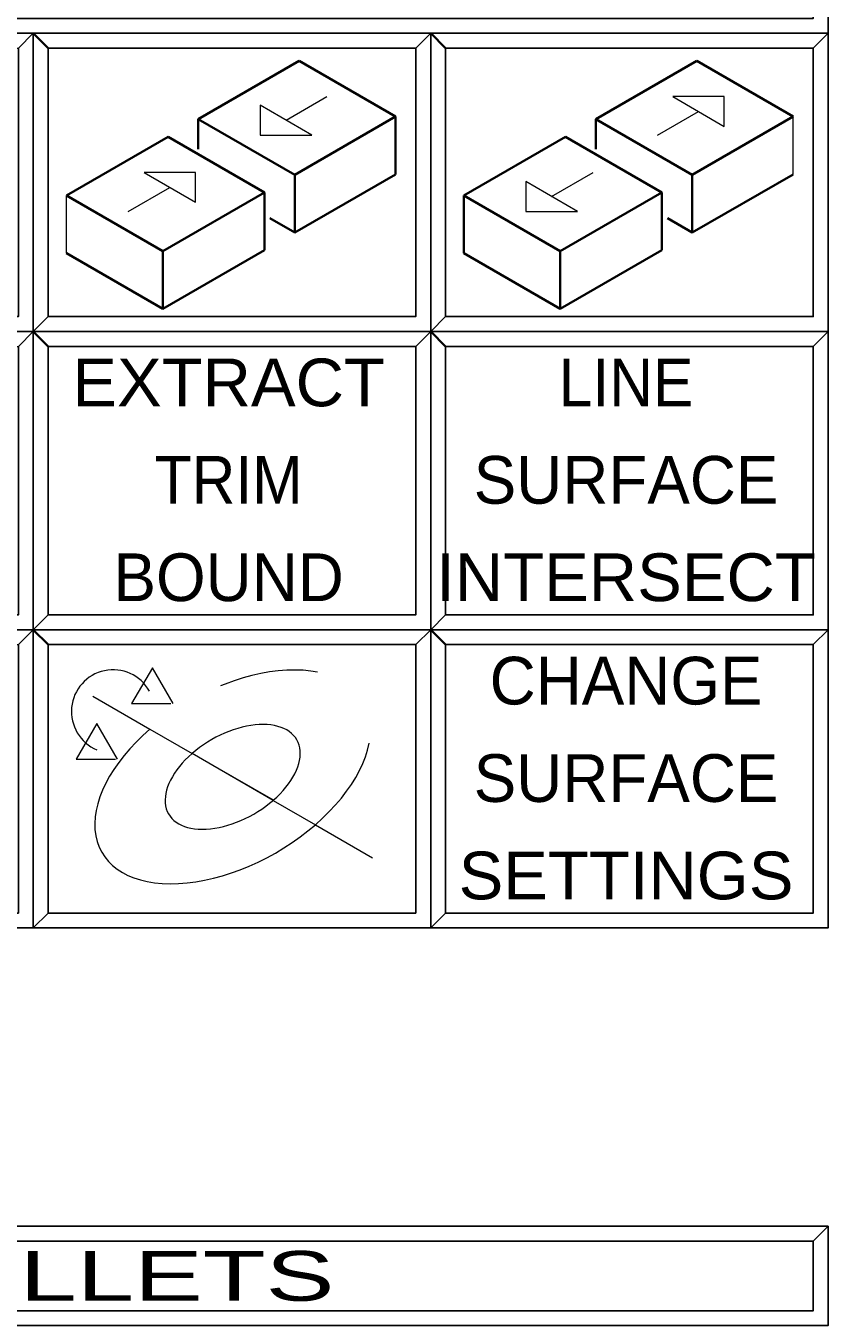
# Model space of a CAD drawing. Extents: x 95906.9 to 95918.9, y 90964.8 to 90972.9.
# Drawn here: x 95915.322 to 95916.13, y 90966.869 to 90968.169 of the extents above; entities that cross this region are included whole.
import ezdxf
from ezdxf.enums import TextEntityAlignment as Align

# ---------------------------------------------------------------- set-up
doc = ezdxf.new("R2010")
doc.units = 0
doc.header["$LTSCALE"] = 0.019
doc.linetypes.add('MEDIUM_DASHED', pattern=[4.5, 3, -1.5])
for name, color, linetype, lineweight in [('1', 7, 'Continuous', 25), ('11', 7, 'Continuous', 25), ('18', 7, 'Continuous', 25), ('2', 7, 'Continuous', 13), ('3', 7, 'Continuous', 25), ('4', 7, 'Continuous', 35), ('6', 7, 'Continuous', 35), ('7', 7, 'Continuous', 35)]:
    doc.layers.add(name, color=color, linetype=linetype, lineweight=lineweight)

msp = doc.modelspace()

# ---------------------------------------------------------------- linework, layer by layer
at = {"layer": '1'}
for points in [[(95914.5298, 90968.1617), (95916.1298, 90968.1617), (95916.1298, 90968.2617), (95914.5298, 90968.2617)], [(95914.9298, 90967.8617), (95915.3298, 90967.8617), (95915.3298, 90968.1617), (95914.9298, 90968.1617)], [(95915.3298, 90967.8617), (95915.7298, 90967.8617), (95915.7298, 90968.1617), (95915.3298, 90968.1617)], [(95915.7298, 90967.8617), (95916.1298, 90967.8617), (95916.1298, 90968.1617), (95915.7298, 90968.1617)], [(95914.9298, 90967.5617), (95915.3298, 90967.5617), (95915.3298, 90967.8617), (95914.9298, 90967.8617)], [(95915.3298, 90967.5617), (95915.7298, 90967.5617), (95915.7298, 90967.8617), (95915.3298, 90967.8617)], [(95915.7298, 90967.5617), (95916.1298, 90967.5617), (95916.1298, 90967.8617), (95915.7298, 90967.8617)], [(95914.9298, 90967.2617), (95915.3298, 90967.2617), (95915.3298, 90967.5617), (95914.9298, 90967.5617)], [(95915.3298, 90967.2617), (95915.7298, 90967.2617), (95915.7298, 90967.5617), (95915.3298, 90967.5617)], [(95915.7298, 90967.2617), (95916.1298, 90967.2617), (95916.1298, 90967.5617), (95915.7298, 90967.5617)], [(95914.5298, 90966.8617), (95916.1298, 90966.8617), (95916.1298, 90966.9617), (95914.5298, 90966.9617)]]:
    msp.add_lwpolyline(points, close=True, dxfattribs=at)
at = {"layer": '11'}
for points in [[(95915.3448, 90967.8767), (95915.7148, 90967.8767), (95915.7148, 90968.1467), (95915.3448, 90968.1467)], [(95915.7448, 90967.8767), (95916.1148, 90967.8767), (95916.1148, 90968.1467), (95915.7448, 90968.1467)], [(95915.3448, 90967.5767), (95915.7148, 90967.5767), (95915.7148, 90967.8467), (95915.3448, 90967.8467)], [(95915.7448, 90967.5767), (95916.1148, 90967.5767), (95916.1148, 90967.8467), (95915.7448, 90967.8467)], [(95915.3448, 90967.2767), (95915.7148, 90967.2767), (95915.7148, 90967.5467), (95915.3448, 90967.5467)], [(95915.7448, 90967.2767), (95916.1148, 90967.2767), (95916.1148, 90967.5467), (95915.7448, 90967.5467)]]:
    msp.add_lwpolyline(points, close=True, dxfattribs=at)
at = {"layer": '18'}
msp.add_lwpolyline([(95914.5448, 90966.8767), (95916.1148, 90966.8767), (95916.1148, 90966.9467), (95914.5448, 90966.9467)], close=True, dxfattribs=at)
at = {"layer": '2'}
for points in [[(95914.9298, 90968.1617), (95914.9298, 90967.8617), (95914.9448, 90967.8767), (95914.9448, 90968.1467), (95915.3148, 90968.1467), (95915.3298, 90968.1617)], [(95915.3298, 90968.1617), (95915.3298, 90967.8617), (95915.3448, 90967.8767), (95915.3448, 90968.1467), (95915.7148, 90968.1467), (95915.7298, 90968.1617)], [(95915.7298, 90968.1617), (95915.7298, 90967.8617), (95915.7448, 90967.8767), (95915.7448, 90968.1467), (95916.1148, 90968.1467), (95916.1298, 90968.1617)], [(95914.9298, 90967.8617), (95914.9298, 90967.5617), (95914.9448, 90967.5767), (95914.9448, 90967.8467), (95915.3148, 90967.8467), (95915.3298, 90967.8617)], [(95915.3298, 90967.8617), (95915.3298, 90967.5617), (95915.3448, 90967.5767), (95915.3448, 90967.8467), (95915.7148, 90967.8467), (95915.7298, 90967.8617)], [(95915.7298, 90967.8617), (95915.7298, 90967.5617), (95915.7448, 90967.5767), (95915.7448, 90967.8467), (95916.1148, 90967.8467), (95916.1298, 90967.8617)], [(95914.9298, 90967.5617), (95914.9298, 90967.2617), (95914.9448, 90967.2767), (95914.9448, 90967.5467), (95915.3148, 90967.5467), (95915.3298, 90967.5617)], [(95915.3298, 90967.5617), (95915.3298, 90967.2617), (95915.3448, 90967.2767), (95915.3448, 90967.5467), (95915.7148, 90967.5467), (95915.7298, 90967.5617)], [(95915.7298, 90967.5617), (95915.7298, 90967.2617), (95915.7448, 90967.2767), (95915.7448, 90967.5467), (95916.1148, 90967.5467), (95916.1298, 90967.5617)], [(95914.5298, 90966.9617), (95914.5298, 90966.8617), (95914.5448, 90966.8767), (95914.5448, 90966.9467), (95916.1148, 90966.9467), (95916.1298, 90966.9617)]]:
    msp.add_lwpolyline(points, close=True, dxfattribs=at)
at = {"layer": '3'}
for points in [[(95914.5298, 90968.1617), (95916.1298, 90968.1617), (95916.1298, 90968.2617), (95916.1148, 90968.2467), (95916.1148, 90968.1767), (95914.5448, 90968.1767)], [(95914.9298, 90967.8617), (95915.3298, 90967.8617), (95915.3298, 90968.1617), (95915.3148, 90968.1467), (95915.3148, 90967.8767), (95914.9448, 90967.8767)], [(95915.3298, 90967.8617), (95915.7298, 90967.8617), (95915.7298, 90968.1617), (95915.7148, 90968.1467), (95915.7148, 90967.8767), (95915.3448, 90967.8767)], [(95915.7298, 90967.8617), (95916.1298, 90967.8617), (95916.1298, 90968.1617), (95916.1148, 90968.1467), (95916.1148, 90967.8767), (95915.7448, 90967.8767)], [(95914.9298, 90967.5617), (95915.3298, 90967.5617), (95915.3298, 90967.8617), (95915.3148, 90967.8467), (95915.3148, 90967.5767), (95914.9448, 90967.5767)], [(95915.3298, 90967.5617), (95915.7298, 90967.5617), (95915.7298, 90967.8617), (95915.7148, 90967.8467), (95915.7148, 90967.5767), (95915.3448, 90967.5767)], [(95915.7298, 90967.5617), (95916.1298, 90967.5617), (95916.1298, 90967.8617), (95916.1148, 90967.8467), (95916.1148, 90967.5767), (95915.7448, 90967.5767)], [(95914.9298, 90967.2617), (95915.3298, 90967.2617), (95915.3298, 90967.5617), (95915.3148, 90967.5467), (95915.3148, 90967.2767), (95914.9448, 90967.2767)], [(95915.3298, 90967.2617), (95915.7298, 90967.2617), (95915.7298, 90967.5617), (95915.7148, 90967.5467), (95915.7148, 90967.2767), (95915.3448, 90967.2767)], [(95915.7298, 90967.2617), (95916.1298, 90967.2617), (95916.1298, 90967.5617), (95916.1148, 90967.5467), (95916.1148, 90967.2767), (95915.7448, 90967.2767)], [(95914.5298, 90966.8617), (95916.1298, 90966.8617), (95916.1298, 90966.9617), (95916.1148, 90966.9467), (95916.1148, 90966.8767), (95914.5448, 90966.8767)]]:
    msp.add_lwpolyline(points, close=True, dxfattribs=at)
at = {"layer": '4'}
for p, q in [((95915.3448, 90968.1467), (95915.3298, 90968.1617)), ((95915.7448, 90968.1467), (95915.7298, 90968.1617)), ((95915.3448, 90967.8467), (95915.3298, 90967.8617)), ((95915.7448, 90967.8467), (95915.7298, 90967.8617)), ((95915.3448, 90967.5467), (95915.3298, 90967.5617)), ((95915.7448, 90967.5467), (95915.7298, 90967.5617))]:
    msp.add_line(p, q, dxfattribs=at)
at = {"layer": '6'}
for p, q in [((95915.4959, 90968.0752), (95915.5975, 90968.134)), ((95915.6945, 90968.078), (95915.5975, 90968.134)), ((95915.8959, 90968.0752), (95915.9975, 90968.134)), ((95916.0945, 90968.078), (95915.9975, 90968.134)), ((95915.4959, 90968.0451), (95915.4959, 90968.0752)), ((95915.5929, 90968.0193), (95915.4959, 90968.0752)), ((95915.5929, 90968.0193), (95915.6945, 90968.078)), ((95915.6945, 90968.0197), (95915.6945, 90968.078)), ((95915.8959, 90968.0451), (95915.8959, 90968.0752)), ((95915.9929, 90968.0193), (95915.8959, 90968.0752)), ((95915.9929, 90968.0193), (95916.0945, 90968.078)), ((95915.3632, 90967.9985), (95915.4656, 90968.0577)), ((95915.5625, 90968.0017), (95915.4656, 90968.0577)), ((95915.7632, 90967.9985), (95915.8656, 90968.0577)), ((95915.9625, 90968.0017), (95915.8656, 90968.0577)), ((95915.5929, 90967.9612), (95915.6945, 90968.0197)), ((95915.5929, 90967.9612), (95915.5929, 90968.0193)), ((95915.9929, 90967.9612), (95916.0945, 90968.0197)), ((95915.9929, 90967.9612), (95915.9929, 90968.0193)), ((95915.4601, 90967.9425), (95915.3632, 90967.9985)), ((95915.4601, 90967.9425), (95915.5625, 90968.0017)), ((95915.5625, 90967.9436), (95915.5625, 90968.0017)), ((95915.8601, 90967.9425), (95915.7632, 90967.9985)), ((95915.8601, 90967.9425), (95915.9625, 90968.0017)), ((95915.9625, 90967.9436), (95915.9625, 90968.0017)), ((95915.5929, 90967.9612), (95915.568, 90967.9757)), ((95915.9929, 90967.9612), (95915.968, 90967.9757)), ((95915.4601, 90967.8846), (95915.5625, 90967.9436)), ((95915.4601, 90967.8846), (95915.4601, 90967.9425)), ((95915.8601, 90967.8846), (95915.9625, 90967.9436)), ((95915.8601, 90967.8846), (95915.8601, 90967.9425)), ((95915.4601, 90967.8846), (95915.3632, 90967.9406))]:
    msp.add_line(p, q, dxfattribs=at)
at = {"layer": '6', "lineweight": 13}
for p, q in [((95915.5843, 90968.0743), (95915.6252, 90968.098)), ((95915.9582, 90968.0593), (95915.9992, 90968.083)), ((95916.0945, 90968.0197), (95916.0945, 90968.078)), ((95915.8514, 90967.9976), (95915.8932, 90968.0217)), ((95915.3632, 90967.9406), (95915.3632, 90967.9985)), ((95915.4254, 90967.9825), (95915.4673, 90968.0067)), ((95915.3448, 90967.5467), (95915.6148, 90967.5467)), ((95915.3897, 90967.495), (95915.4472, 90967.4618)), ((95915.4288, 90967.4875), (95915.4684, 90967.4875)), ((95915.4472, 90967.4618), (95915.4897, 90967.4373)), ((95915.5714, 90967.3902), (95915.4896, 90967.4372)), ((95915.5713, 90967.3901), (95915.4897, 90967.4373)), ((95915.3728, 90967.4314), (95915.4124, 90967.4314)), ((95915.5713, 90967.3901), (95915.5714, 90967.3902)), ((95915.5713, 90967.3901), (95915.6138, 90967.3656)), ((95915.6138, 90967.3656), (95915.6713, 90967.3324))]:
    msp.add_line(p, q, dxfattribs=at)
for points in [[(95915.5582, 90968.0894), (95915.5582, 90968.0593), (95915.6103, 90968.0593)], [(95915.9733, 90968.098), (95916.0252, 90968.068), (95916.0252, 90968.098)], [(95915.4932, 90968.0217), (95915.4413, 90968.0217), (95915.4932, 90967.9917)], [(95915.8254, 90968.0126), (95915.8254, 90967.9825), (95915.8775, 90967.9825)]]:
    msp.add_lwpolyline(points, close=True, dxfattribs=at)
at = {"layer": '6'}
msp.add_lwpolyline([(95915.8601, 90967.8846), (95915.7632, 90967.9406), (95915.7632, 90967.9985)], dxfattribs=at)
at = {"layer": '6', "lineweight": 13}
for points in [[(95915.4705, 90967.4875), (95915.4497, 90967.5235), (95915.4288, 90967.4875)], [(95915.4145, 90967.4314), (95915.3937, 90967.4674), (95915.3728, 90967.4314)]]:
    msp.add_lwpolyline(points, dxfattribs=at)
msp.add_arc((95915.4101, 90967.4795), 0.0419, 29.391, 247.0718, dxfattribs=at)
at = {"layer": '6', "linetype": 'MEDIUM_DASHED', "lineweight": 13}
msp.add_ellipse((95915.5305, 90967.4137), major_axis=(0.1317, 0.076), ratio=0.57735, start_param=5.034098, end_param=8.175722, dxfattribs=at)
at = {"layer": '6', "lineweight": 13}
for major_axis, start_param, end_param in [((0.1317, 0.076), 1.892505, 5.03413), ((0.0645, 0.0373), 5.033697, 8.175976), ((0.0645, 0.0373), 5.033697, 8.175976), ((0.0645, 0.0373), 1.893524, 5.035586)]:
    msp.add_ellipse((95915.5305, 90967.4137), major_axis=major_axis, ratio=0.57735, start_param=start_param, end_param=end_param, dxfattribs=at)

# ---------------------------------------------------------------- texts
at = {"layer": '6'}
for s, width, p in [('EXTRACT', 1.05, (95915.5264, 90967.7865)), ('LINE', 0.95, (95915.9264, 90967.7865)), ('TRIM', 0.95, (95915.5264, 90967.6885)), ('INTERSECT', 1.05, (95915.9263, 90967.5905)), ('SETTINGS', 1.05, (95915.9264, 90967.2905))]:
    msp.add_text(s, height=0.048, dxfattribs=dict(at, width=width)).set_placement(p, align=Align.CENTER)
for s, p in [('SURFACE', (95915.9264, 90967.6885)), ('BOUND', (95915.5264, 90967.5905)), ('CHANGE', (95915.9264, 90967.4865)), ('SURFACE', (95915.9264, 90967.3885))]:
    msp.add_text(s, height=0.048, dxfattribs=at).set_placement(p, align=Align.CENTER)
at = {"layer": '7', "width": 1.55}
msp.add_text('      3D FILLETS    ', height=0.05, dxfattribs=at).set_placement((95915.3189, 90966.8867), align=Align.CENTER)

doc.saveas('drawing.dxf')
